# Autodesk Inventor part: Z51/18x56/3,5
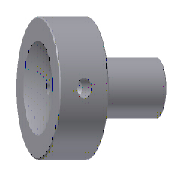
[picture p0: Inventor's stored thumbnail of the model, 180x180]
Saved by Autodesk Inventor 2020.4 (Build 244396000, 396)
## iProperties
Created: 2019-01
Part Number: Z51/18x56/3,5
Material: 1.2826
Description: Sprue Bushing
Document SubType Name: Modeling
Designer: mel
Standard Revision: 1
Manufacturer: HASCO
Language: fr-FR
Size Designation: 18x56/3,5
Categories: <MemberInstance><Categories><Category DisplayName="Moule" InternalName="349578f2-f4d4-4954-8c09-8e99297a61c0" Mnemonic="MOLD"><Category DisplayName="Canal d'inj
Density: 7.82 g/cm^3
Appearance: Par défaut
IsCustomPart: 1
Author: mel
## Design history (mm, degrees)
sketch "Sketch1"
  geometry: L1 (0, -27.2)-(0, 23.2) reference; L2 (1.75, 18)-(19, 18); L3 (19, 18)-(19, 0); L4 (19, 0)-(12, 0); L5 (9, -3)-(9, -56); L6 (9, -56)-(3.688, -56); L7 (3.688, -56)-(1.75, 18); A1 r 3 centre (12, -3) between (12, 0) and (9, -3); 2 further points
  constraints: 12 end point, 3 parallel, 2 perpendicular, 2 point on circle, 2 point on line, 2 tangent, 1 centre point
  dimensions: "d0" = 18 diameter of L5 L1 (= D); "d3" = 38 diameter of L3 L1 (= d1); "d6" = 1.5 deg angle of L7 L1 (= 0.5 x Taper); "d7" = 18 distance between parallel lines of L4 L2 (= K_); "d8" = 56 distance between parallel lines of L4 L6 (= L); "d9" = 3 radius of A1 (= R3); "d62" = 3.5 diameter of point (1.75, 18) L1 (= d_); "d63" = 0 distance from line of point (1.75, 18) L2 (computed from Rd)
revolve "Revolution1" sketch "Sketch1" stored, may be unused: angle "d10" = 90 deg
sketch "Sketch2"
  geometry: L1 (0, -32.79)-(0, 56.739) reference; L2 (3.688, -56)-(1.75, 18) reference; L3 (-19, 18)-(19, 18) reference; L4 (0, 48.901)-(0, 17.901); A1 r 15.5 centre (0, 33.401) between (0, 17.901) and (0, 48.901); 2 further points
  constraints: 3 point on circle, 3 point on line, 2 end point, 1 centre point, 1 midpoint
  dimensions: "d64" = 0 distance from line of point (1.75, 18) L3 (computed from Rd); "d67" = 15.5 radius of A1 (= Rk)
revolve "Revolution2" sketch "Sketch2" stored, may be unused: angle "d13" = 90 deg
workplane "Work Plane1"
sketch "Sketch3"
  geometry: 2 further points
  constraints: 1 vertical alignment
  dimensions: "d43" = 9 distance of point (0, -9) point (0, 0) (= 0.5 x K_)
hole "Hole1" sketch "Sketch3" at (0, 0) diameter "d15" = 4 (= pd1); stored, may be unused: countersink angle "d19" = 90 deg, drill point angle "d21" = 118 deg; dims "d16" = 6, "d17" = 4, "d18" = 2, "d20" = 6 (= pl1)
chamfer "Chamfer1" distance "d22" = 0.3; stored, may be unused: second distance "d23" = 2, angle "d24" = 45 deg
sketch "Sketch4"
  geometry: L1 (0, -30.4)-(0, 42.4) reference; L2 (0, 36)-(19.5, 36); L3 (19.5, 36)-(19.5, 0); L4 (9, -56)-(0, -56); L5 (0, -56)-(0, 36); L6 (9, -3)-(9, -56); L7 (12, 0)-(19.5, 0); L8 (12, 0)-(9, -3); 2 further points
  constraints: 14 end point, 4 point on line, 2 horizontal, 2 parallel, 1 perpendicular, 1 vertical
  dimensions: "d56" = 3 distance of L7.start point (9, 0) (= R3_CS); "d57" = 3 distance of L6.start point (9, 0) (= d56); "d58" = 39 diameter of L3 L1 (= d1_CS); "d59" = 36 distance between parallel lines of L7 L2 (= K_CS); "d60" = 18 diameter of L6 L1 (= D_CS); "d61" = 56 distance between parallel lines of L7 L4 (= L_CS)
feature "RevolutionSrf1" sketch "Sketch4" dims angle "d33" = 90 deg
body "Solid1"
body "Srf1"
other parameters: "L" = 56 [user parameter; used in 1 equation term], "d1" = 38 [user parameter; used in 1 equation term], "d_" = 3.5 [user parameter; used in 1 equation term], "D" = 18 [user parameter; used in 1 equation term], "K_" = 18 [user parameter; used in 2 equation terms], "R" = 0 [user parameter], "Taper" = 3 deg [user parameter; used in 1 equation term], "Rd" = 0 [user parameter; used in 2 equation terms], "R3" = 3 [user parameter; used in 1 equation term], "pd1" = 4 [user parameter; used in 1 equation term], "d1_CS" = 39 [user parameter; used in 1 equation term], "K_CS" = 36 [user parameter; used in 1 equation term], "d44" = 0, "d45" = 0, "d46" = 0, "L_CS" = 56 [user parameter; used in 1 equation term], "D_CS" = 18 [user parameter; used in 1 equation term], "pl1" = 6 [user parameter; used in 1 equation term], "R3_CS" = 3 [user parameter; used in 1 equation term], "Rk" = 15.5 [user parameter; used in 1 equation term]
